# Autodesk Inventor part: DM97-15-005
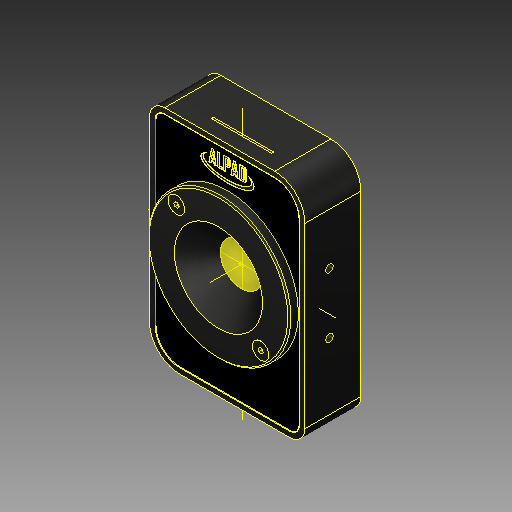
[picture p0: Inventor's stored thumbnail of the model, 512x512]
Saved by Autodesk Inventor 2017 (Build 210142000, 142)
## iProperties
Created: 2016-03
Part Number: DM97-15-005
Material: Generic
Description: STEP AP203
Document SubType Name: Modeling
Designer: Radek
Density: 1 g/cm^3
Appearance: Default
Sending System: SolidWorks 2015
Preprocessor: SwSTEP 2.0
Title: ASM-DM97-15-005.STEP
Revision Number: ANY
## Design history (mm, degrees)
feature "Composite1"
workpoint "Work Point1"
  workaxis "Work Axis1"
workaxis "Work Axis2"
workaxis "Work Axis3"
body "Srf1"
